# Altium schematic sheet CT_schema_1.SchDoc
size 531 x 513 mm
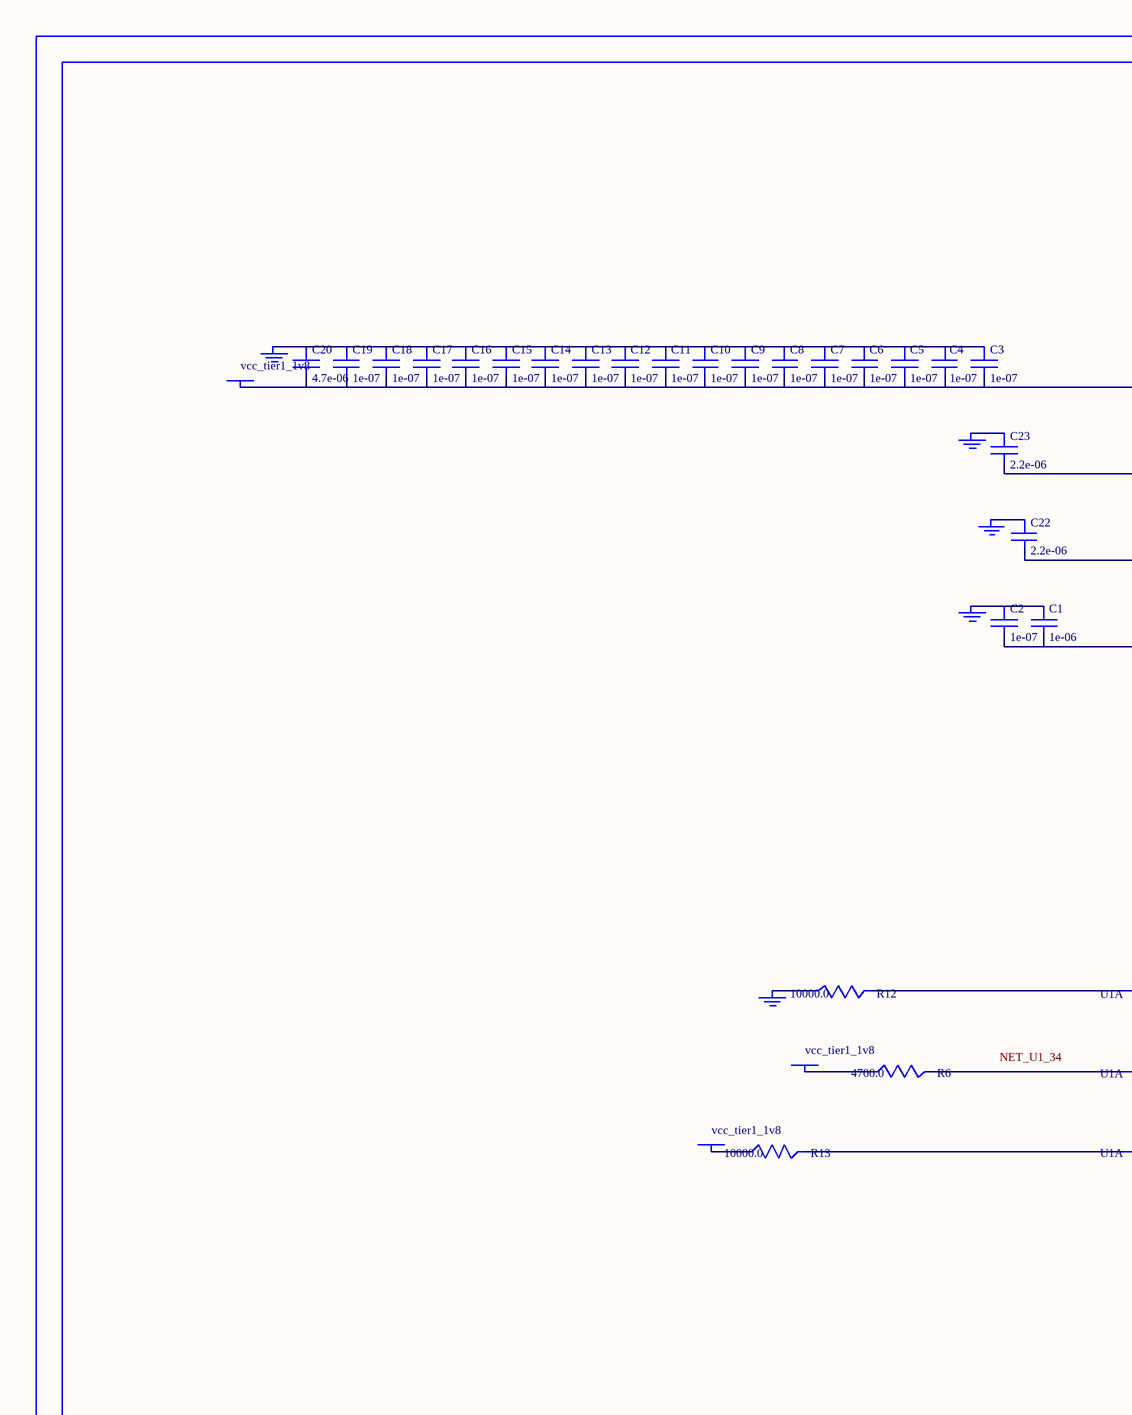
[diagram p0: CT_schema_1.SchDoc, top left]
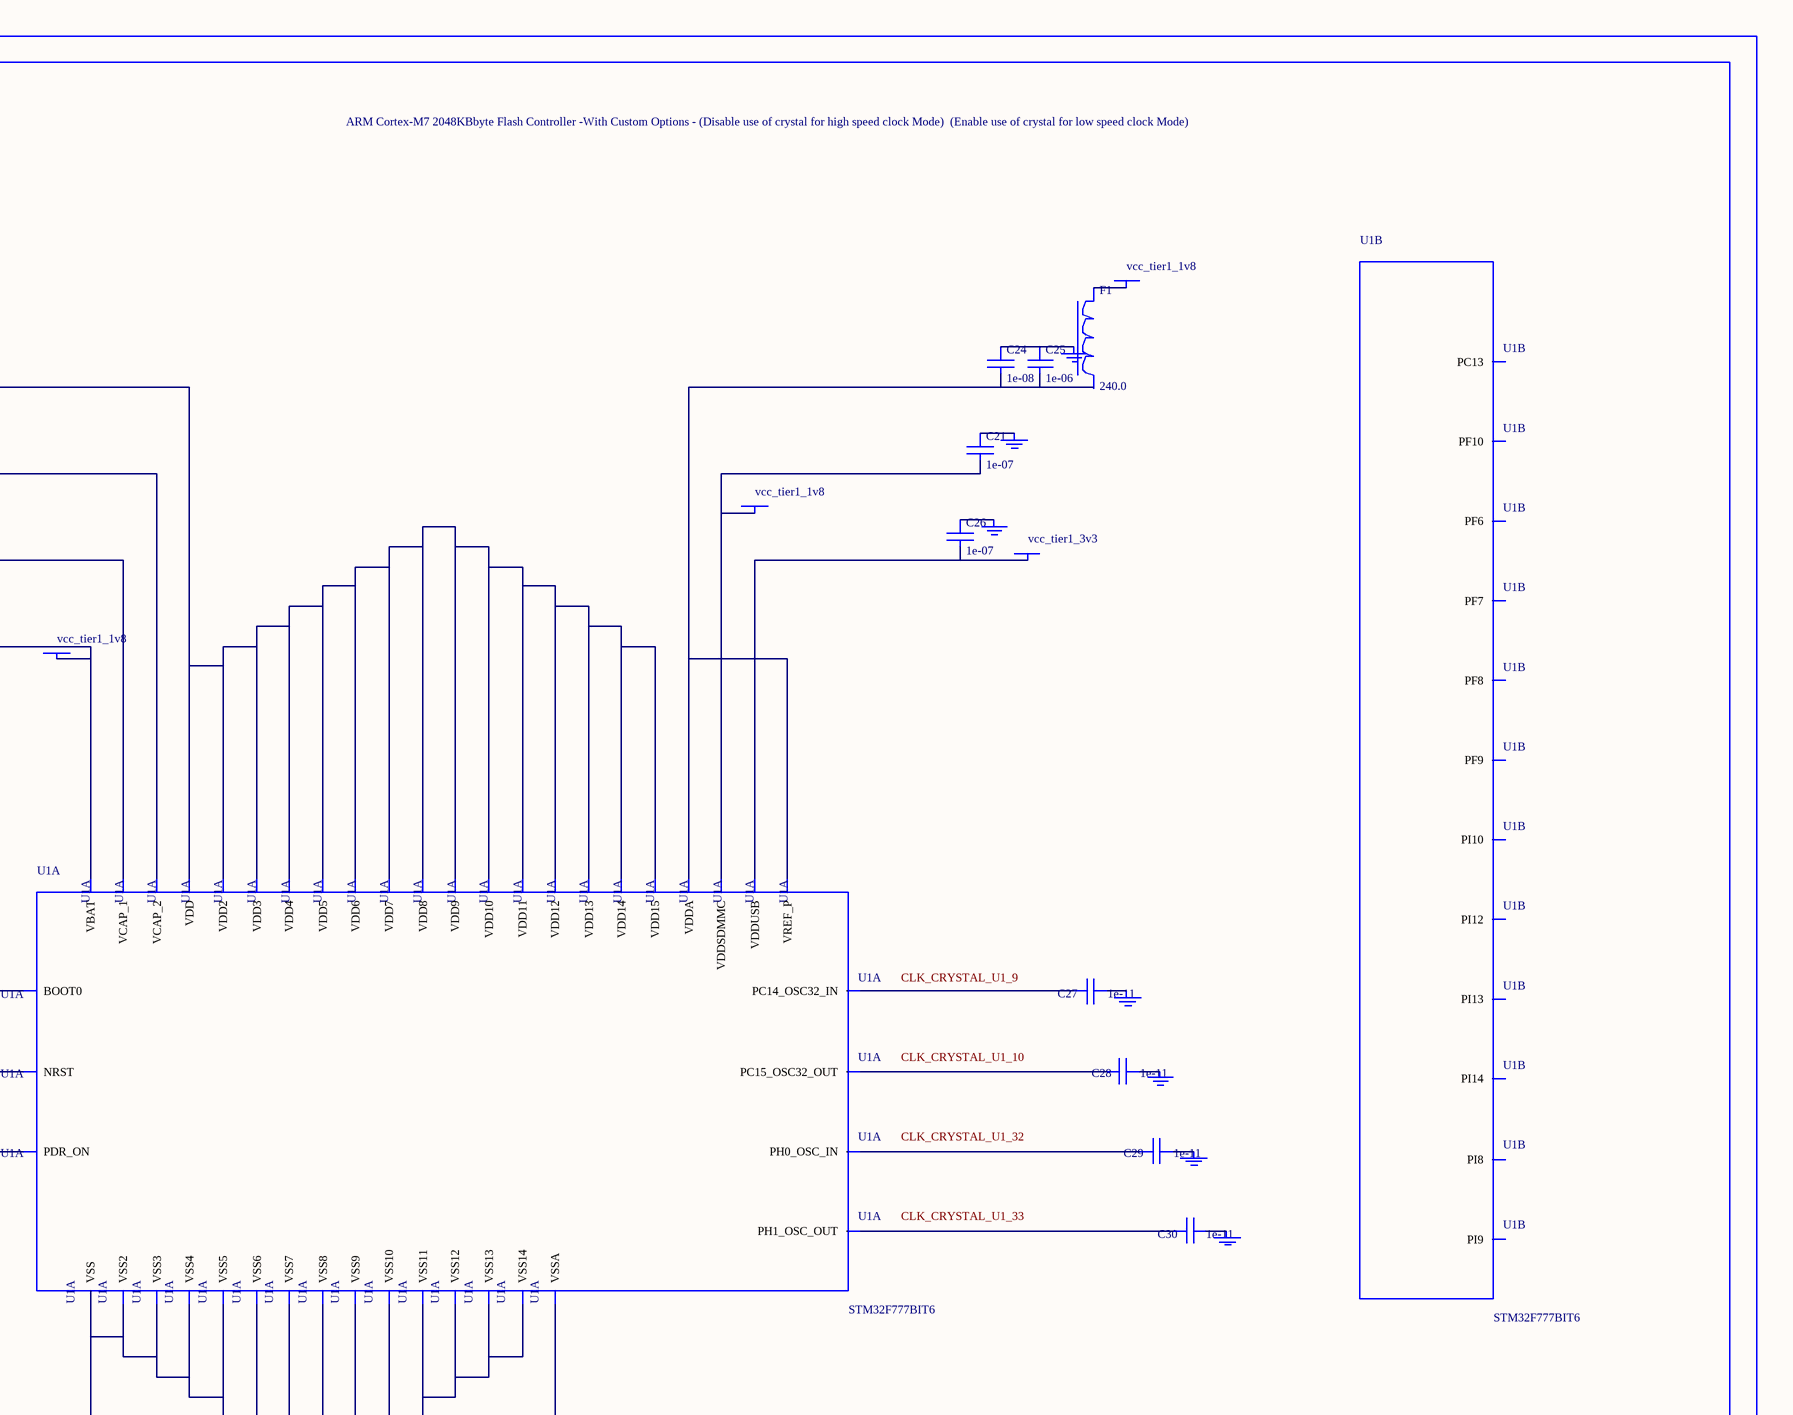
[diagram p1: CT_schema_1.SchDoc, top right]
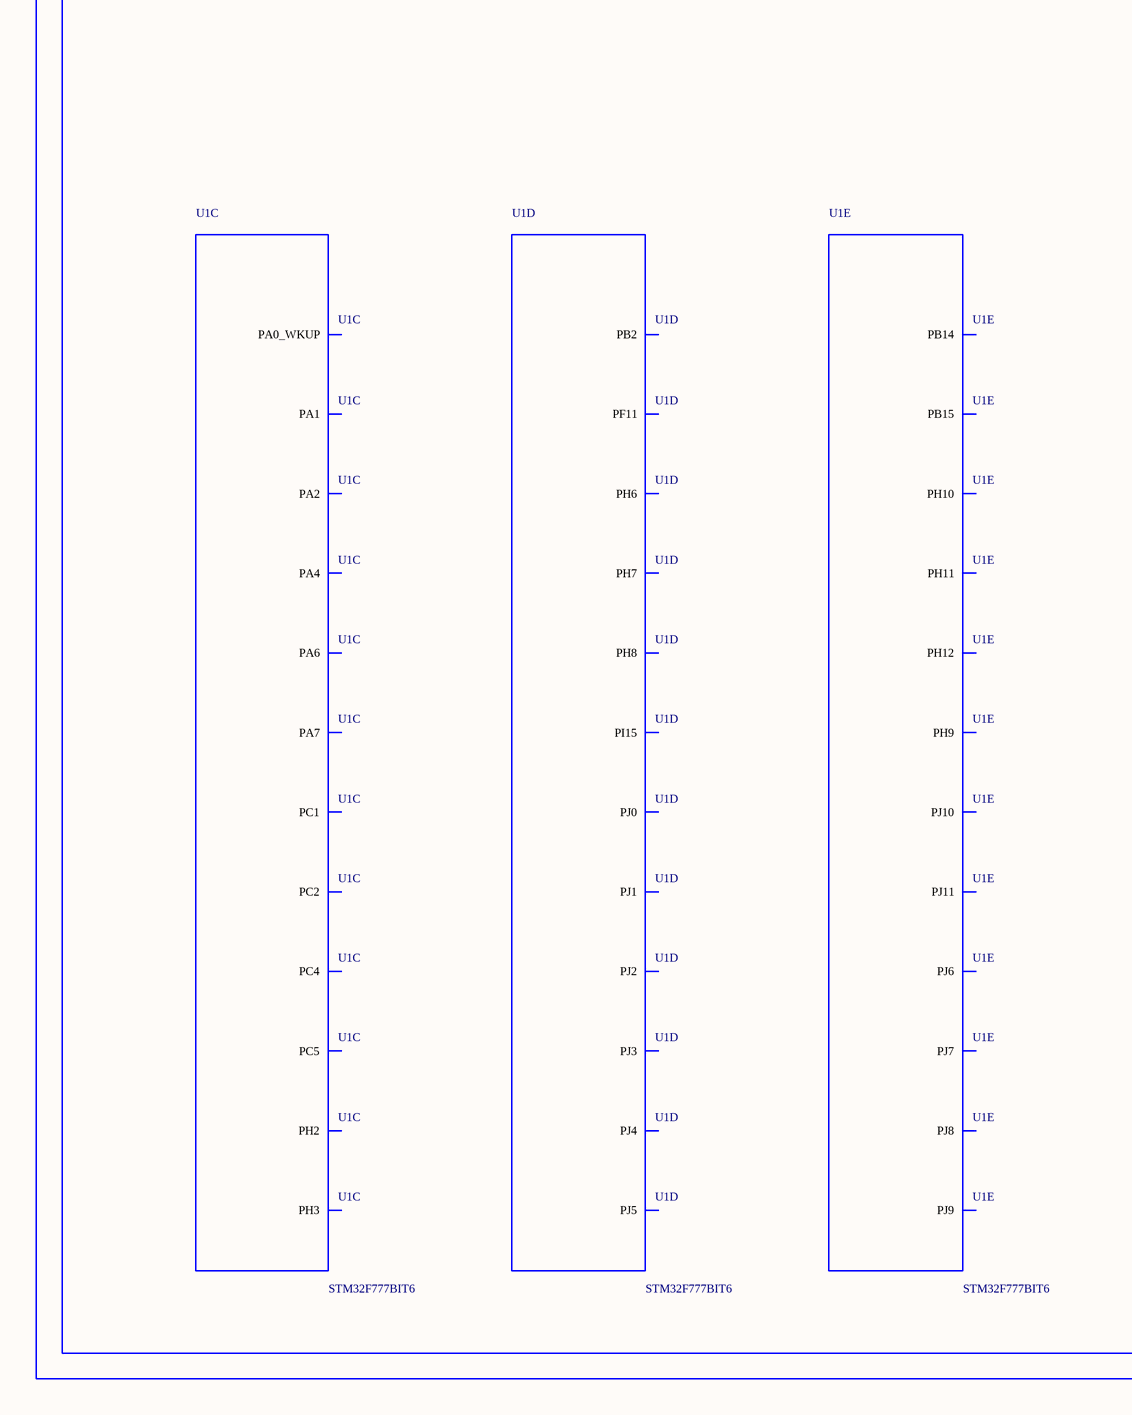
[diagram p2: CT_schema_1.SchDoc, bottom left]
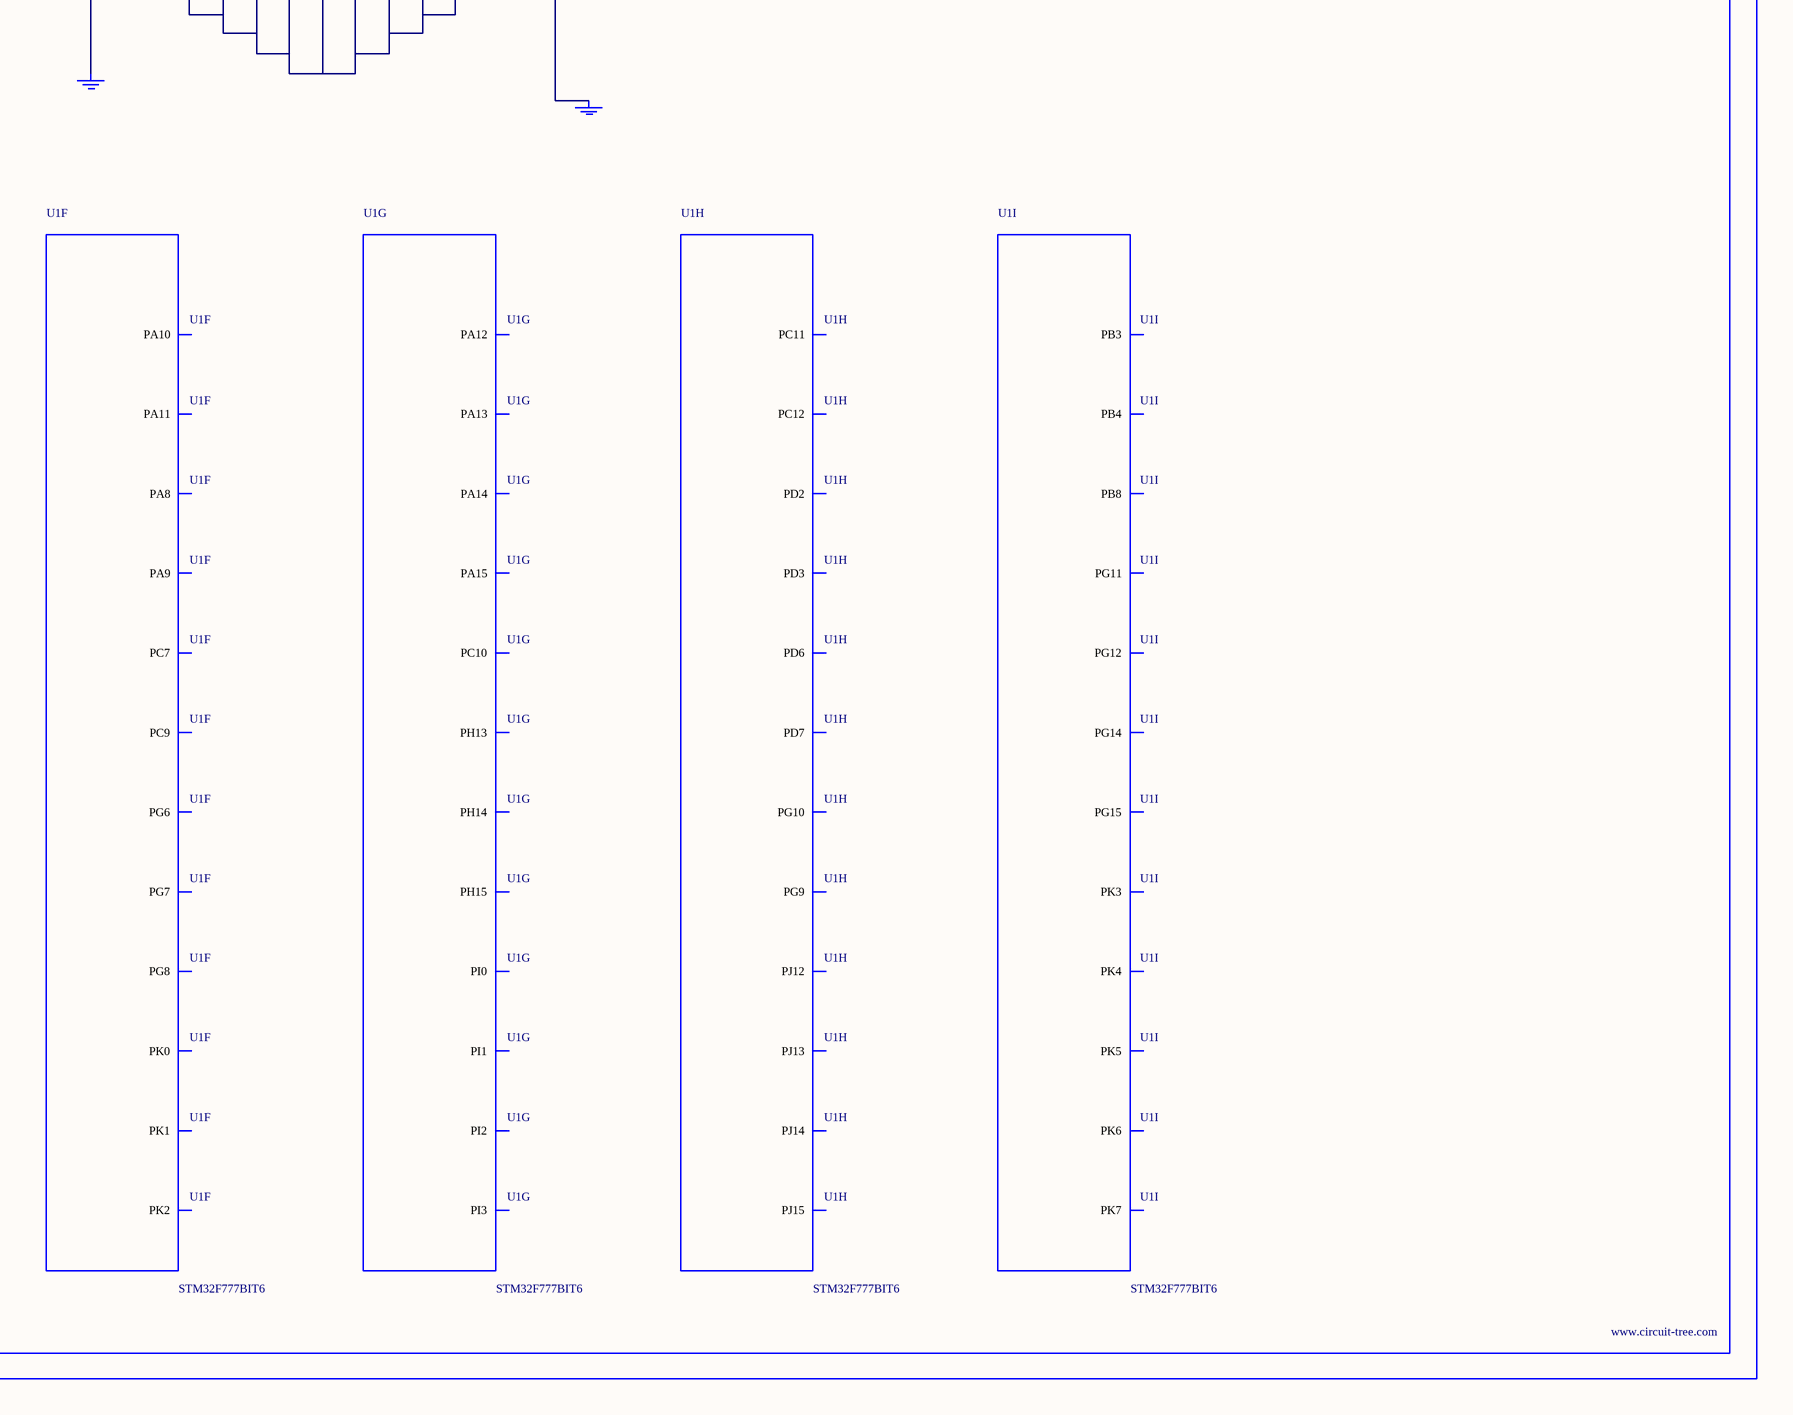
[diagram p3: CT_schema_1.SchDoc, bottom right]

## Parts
BORDER0  (no value)
C1  1e-06  [C0603]
C2  1e-07  [C0603]
C3  1e-07  [C0603]
C4  1e-07  [C0603]
C5  1e-07  [C0603]
C6  1e-07  [C0603]
C7  1e-07  [C0603]
C8  1e-07  [C0603]
C9  1e-07  [C0603]
C10  1e-07  [C0603]
C11  1e-07  [C0603]
C12  1e-07  [C0603]
C13  1e-07  [C0603]
C14  1e-07  [C0603]
C15  1e-07  [C0603]
C16  1e-07  [C0603]
C17  1e-07  [C0603]
C18  1e-07  [C0603]
C19  1e-07  [C0603]
C20  4.7e-06  [C0603]
C21  1e-07  [C0603]
C22  2.2e-06  [C0603]
C23  2.2e-06  [C0603]
C24  1e-08  [C0603]
C25  1e-06  [C0603]
C26  1e-07  [C0603]
C27  1e-11  [C0402]
C28  1e-11  [C0402]
C29  1e-11  [C0402]
C30  1e-11  [C0402]
F1  240.0  [L0603]
GND_INSTANCE_0_0  (no value)
GND_INSTANCE_0_1  (no value)
GND_INSTANCE_0_2  (no value)
GND_INSTANCE_0_3  (no value)
GND_INSTANCE_0_4  (no value)
GND_INSTANCE_0_5  (no value)
GND_INSTANCE_0_6  (no value)
GND_INSTANCE_0_7  (no value)
GND_INSTANCE_0_8  (no value)
GND_INSTANCE_0_9  (no value)
GND_INSTANCE_0_10  (no value)
GND_INSTANCE_0_11  (no value)
GND_INSTANCE_0_12  (no value)
GND_INSTANCE_0_13  (no value)
POWER_INSTANCE_0_0  vcc_tier1_1v8
POWER_INSTANCE_0_1  vcc_tier1_1v8
POWER_INSTANCE_0_2  vcc_tier1_1v8
POWER_INSTANCE_0_3  vcc_tier1_3v3
POWER_INSTANCE_0_4  vcc_tier1_1v8
POWER_INSTANCE_0_5  vcc_tier1_1v8
POWER_INSTANCE_0_6  vcc_tier1_1v8
R6  4700.0  [R0603]
R12  10000.0  [R0603]
R13  10000.0  [R0603]
U1  STM32F777BIT6  [LQFP208]  (parts A,B,C,D,E,F,G,H,I of 15)

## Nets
NetC1_1: C1.1 C2.1 GND_INSTANCE_0_0.0(GND)
NetC1_2: C1.2 C2.2 POWER_INSTANCE_0_0.0(PWR) U1.6(VBAT)
NetC3_1: C3.1 C4.1 C5.1 C6.1 C7.1 C8.1 C9.1 C10.1 C11.1 C12.1 C13.1 C14.1 C15.1 C16.1 C17.1 C18.1 C19.1 C20.1 GND_INSTANCE_0_3.0(GND)
NetC3_2: C3.2 C4.2 C5.2 C6.2 C7.2 C8.2 C9.2 C10.2 C11.2 C12.2 C13.2 C14.2 C15.2 C16.2 C17.2 C18.2 C19.2 C20.2 POWER_INSTANCE_0_1.0(PWR) U1.15(VDD) U1.26(VDD2) U1.39(VDD3) U1.52(VDD4) U1.59(VDD5) U1.73(VDD6) U1.83(VDD7) U1.94(VDD8) U1.103(VDD9) U1.115(VDD10) U1.124(VDD11) U1.150(VDD12) U1.158(VDD13) U1.185(VDD14) U1.204(VDD15)
NetC21_1: C21.1 GND_INSTANCE_0_11.0(GND)
NetC21_2: C21.2 POWER_INSTANCE_0_4.0(PWR) U1.171(VDDSDMMC)
NetC22_1: C22.1 GND_INSTANCE_0_8.0(GND)
NetC22_2: C22.2 U1.92(VCAP_1)
NetC23_1: C23.1 GND_INSTANCE_0_10.0(GND)
NetC23_2: C23.2 U1.148(VCAP_2)
NetC24_1: C24.1 C25.1 GND_INSTANCE_0_7.0(GND)
NetC24_2: C24.2 C25.2 U1.41(VREF_P) U1.42(VDDA)
NetC26_1: C26.1 GND_INSTANCE_0_9.0(GND)
NetC26_2: C26.2 POWER_INSTANCE_0_3.0(PWR) U1.137(VDDUSB)
NetC27_1: C27.1 GND_INSTANCE_0_1.0(GND)
NetC27_2: C27.2 U1.9(PC14_OSC32_IN)
NetC28_1: C28.1 GND_INSTANCE_0_2.0(GND)
NetC28_2: C28.2 U1.10(PC15_OSC32_OUT)
NetC29_1: C29.1 GND_INSTANCE_0_4.0(GND)
NetC29_2: C29.2 U1.32(PH0_OSC_IN)
NetC30_1: C30.1 GND_INSTANCE_0_5.0(GND)
NetC30_2: C30.2 U1.33(PH1_OSC_OUT)
NetF1_1: F1.1 POWER_INSTANCE_0_2.0(PWR)
NetGND_INSTANCE_0_6_0: GND_INSTANCE_0_6.0(GND) U1.40(VSSA)
NetGND_INSTANCE_0_12_0: GND_INSTANCE_0_12.0(GND) R12.1
NetGND_INSTANCE_0_13_0: GND_INSTANCE_0_13.0(GND) U1.14(VSS) U1.25(VSS2) U1.51(VSS3) U1.60(VSS4) U1.72(VSS5) U1.82(VSS6) U1.93(VSS7) U1.114(VSS8) U1.125(VSS9) U1.136(VSS10) U1.149(VSS11) U1.170(VSS12) U1.184(VSS13) U1.202(VSS14)
NetPOWER_INSTANCE_0_5_0: POWER_INSTANCE_0_5.0(PWR) R13.1
NetPOWER_INSTANCE_0_6_0: POWER_INSTANCE_0_6.0(PWR) R6.1
NetR6_2: R6.2 U1.34(NRST)
NetR12_2: R12.2 U1.197(BOOT0)
NetR13_2: R13.2 U1.203(PDR_ON)

Not connected (* = marked no-connect by the designer): F1 2; U1 7(PI8) 8(PC13) 11(PI9) 12(PI10) 19(PI12) 20(PI13) 21(PI14) 27(PF6) 28(PF7) 29(PF8) 30(PF9) 31(PF10) 36(PC1) 37(PC2) 43(PA0_WKUP) 44(PA1) 45(PA2) 46(PH2) 47(PH3) 53(PA4) 55(PA6) 56(PA7) 57(PC4) 58(PC5) 63(PB2) 64(PI15) 65(PJ0) 66(PJ1) 67(PJ2) 68(PJ3) 69(PJ4) 70(PF11) 95(PJ5) 96(PH6) 97(PH7) 98(PH8) 99(PH9) 100(PH10) 101(PH11) 102(PH12) 106(PB14) 107(PB15) 118(PJ6) 119(PJ7) 120(PJ8) 121(PJ9) 122(PJ10) 123(PJ11) 126(PK0) 127(PK1) 128(PK2) 133(PG6) 134(PG7) 135(PG8) 139(PC7) 141(PC9) 142(PA8) 143(PA9) 144(PA10) 145(PA11) 146(PA12) 147(PA13) 151(PH13) 152(PH14) 153(PH15) 154(PI0) 155(PI1) 156(PI2) 157(PI3) 159(PA14) 160(PA15) 161(PC10) 162(PC11) 163(PC12) 166(PD2) 167(PD3) 172(PD6) 173(PD7) 174(PJ12) 175(PJ13) 176(PJ14) 177(PJ15) 178(PG9) 179(PG10) 180(PG11) 181(PG12) 183(PG14) 186(PK3) 187(PK4) 188(PK5) 189(PK6) 190(PK7) 191(PG15) 192(PB3) 193(PB4) 198(PB8)

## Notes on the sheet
- Labels drawn without touching a wire or pin: CLK_CRYSTAL_U1_9, CLK_CRYSTAL_U1_10, CLK_CRYSTAL_U1_32, CLK_CRYSTAL_U1_33, NET_U1_34

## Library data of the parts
BORDER0 = BORDER_PAGE0
C1 C25 = C0603C105K3RACTU
C2-C19 C21 C26 = 06035C104K4Z2A
C20 = GRM188R6YA475KE15D
C22 C23 = C0603C225K8RACTU
C24 = 06035C103K4Z2A
C27-C30 = C0402C100K3GACTU
F1 = Z0603C241ASMST
GND_INSTANCE_0_0-GND_INSTANCE_0_13 = GND
POWER_INSTANCE_0_0-POWER_INSTANCE_0_6 = PWR
R6 = RC0603JR-074K7L
R12 R13 = RC0603JR-0710KL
